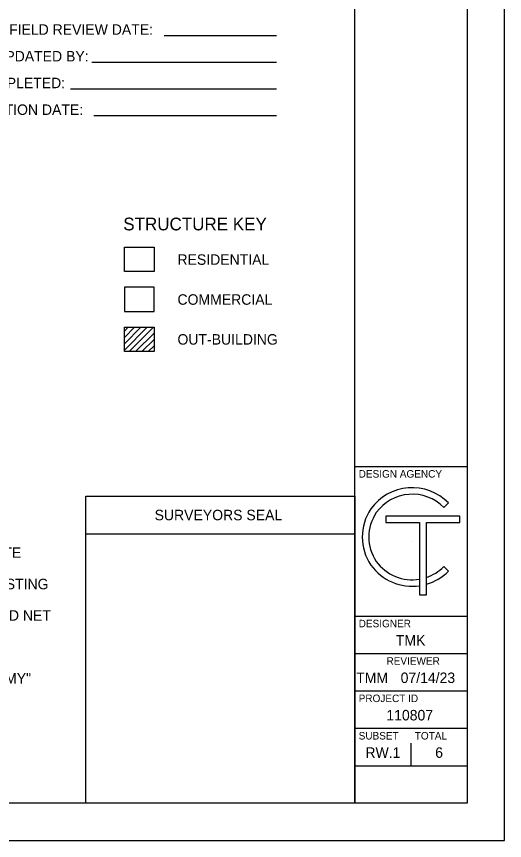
# Model space of a CAD drawing. Extents: x 0 to 34, y 0 to 22.
# Drawn here: x 27.47 to 34, y 0 to 11.01 of the extents above; entities that cross this region are included whole.
import ezdxf

# ---------------------------------------------------------------- set-up
doc = ezdxf.new("R2010")
doc.units = 0
for name, color, linetype in [('SC_Shading1', 7, 'Continuous'), ('SH_Border', 7, 'Continuous'), ('SH_Cut_Line', 7, 'Continuous'), ('SH_Data', 7, 'Continuous'), ('SH_Text', 7, 'Continuous')]:
    doc.layers.add(name, color=color, linetype=linetype)

msp = doc.modelspace()

# ---------------------------------------------------------------- linework, layer by layer
at = {"layer": 'SC_Shading1'}
msp.add_lwpolyline([(28.918, 7.069), (29.315, 7.069), (29.315, 7.395), (28.918, 7.395)], close=True, dxfattribs=at)
at = {"layer": 'SH_Border'}
for p, q in [((32, 0.5), (32, 21.5)), ((32, 5), (33.5, 5)), ((32, 3), (33.5, 3)), ((32, 2.5), (33.5, 2.5)), ((32, 2), (33.5, 2)), ((32, 1.5), (33.5, 1.5)), ((32, 1), (33.5, 1))]:
    msp.add_line(p, q, dxfattribs=at)
msp.add_lwpolyline([(1.5, 21.5), (33.5, 21.5), (33.5, 0.5), (1.5, 0.5)], close=True, dxfattribs=at)
at = {"layer": 'SH_Cut_Line'}
msp.add_lwpolyline([(0, 0), (34, 0), (34, 22), (0, 22)], close=True, dxfattribs=at)
at = {"layer": 'SH_Data'}
for p, q in [((28.4, 4.1), (32, 4.1)), ((32.75, 4), (32.75, 4)), ((32.75, 1), (32.75, 1.3))]:
    msp.add_line(p, q, dxfattribs=at)
msp.add_lwpolyline([(28.4, 4.6), (32, 4.6), (32, 0.5), (28.4, 0.5)], close=True, dxfattribs=at)
at = {"layer": 'SH_Text'}
for p, q in [((29.45, 10.758), (30.953, 10.758)), ((28.48, 10.401), (30.953, 10.401)), ((28.195, 10.044), (30.953, 10.044)), ((28.51, 9.687), (30.953, 9.687)), ((28.918, 6.858), (28.919, 6.86)), ((28.918, 6.808), (28.969, 6.86)), ((28.918, 6.724), (29.054, 6.86)), ((28.918, 6.639), (29.138, 6.86)), ((28.918, 6.554), (29.223, 6.86)), ((28.982, 6.534), (29.308, 6.86)), ((29.067, 6.534), (29.315, 6.782)), ((29.151, 6.534), (29.315, 6.697)), ((29.236, 6.534), (29.315, 6.612)), ((28.918, 6.538), (28.922, 6.534)), ((33.249, 4.513), (33.187, 4.452)), ((33.249, 4.513), (33.187, 4.452)), ((33.402, 4.333), (32.414, 4.333)), ((32.414, 4.333), (32.414, 4.251)), ((33.402, 4.251), (33.402, 4.333)), ((32.414, 4.251), (32.863, 4.251)), ((32.863, 4.251), (32.863, 3.285)), ((32.956, 3.285), (32.956, 4.251)), ((32.956, 4.251), (33.402, 4.251)), ((33.187, 3.66), (33.249, 3.599)), ((33.187, 3.66), (33.249, 3.599)), ((32.863, 3.493), (32.863, 3.405)), ((32.863, 3.493), (32.863, 3.405)), ((32.956, 3.425), (32.956, 3.516)), ((32.956, 3.425), (32.956, 3.516)), ((32.863, 3.285), (32.956, 3.285))]:
    msp.add_line(p, q, dxfattribs=at)
for points in [[(28.918, 7.93), (29.315, 7.93), (29.315, 7.605), (28.918, 7.605)], [(28.918, 6.86), (29.315, 6.86), (29.315, 6.534), (28.918, 6.534)], [(32.863, 4.251), (32.863, 3.285), (32.956, 3.285), (32.956, 4.251), (33.402, 4.251), (33.402, 4.333), (32.414, 4.333), (32.414, 4.251)]]:
    msp.add_lwpolyline(points, close=True, dxfattribs=at)
for centre, radius, start, end in [((32.766, 4.035), 0.68, 44.7027, 144.3276), ((32.766, 4.035), 0.68, 44.7027, 144.3276), ((32.766, 4.035), 0.593, 44.7362, 144.1102), ((32.766, 4.035), 0.593, 44.7362, 144.1102), ((32.764, 4.056), 0.666, 145.7329, 214.2671), ((32.764, 4.056), 0.666, 145.7329, 214.2671), ((32.764, 4.056), 0.579, 145.7266, 214.2734), ((32.764, 4.056), 0.579, 145.7266, 214.2734), ((32.766, 4.078), 0.68, 215.6724, 278.2613), ((32.766, 4.078), 0.68, 215.6724, 278.2613), ((32.766, 4.078), 0.593, 215.8898, 279.4882), ((32.766, 4.078), 0.593, 215.8898, 279.4882), ((32.766, 4.078), 0.593, 288.6992, 315.2638), ((32.766, 4.078), 0.593, 288.6992, 315.2638), ((32.766, 4.078), 0.68, 286.2291, 315.2973), ((32.766, 4.078), 0.68, 286.2291, 315.2973)]:
    msp.add_arc(centre, radius, start, end, dxfattribs=at)

# ---------------------------------------------------------------- texts
at = {"layer": 'SH_Data'}
for s, height, p in [('DESIGN AGENCY', 0.1, (32.05, 4.85)), ('SURVEYORS SEAL', 0.14, (29.321, 4.28)), ('BETWEEN MARCH, 2022 AND MAY, 2022. THE RESULTS OF THAT SURVEY ARE CONTAINED HEREIN. SEE THE SURVEY PARAMETERS NOTE', 0.14, (14.869, 3.778)), ('I HAVE REESTABLISHED THE LOCATIONS OF THE EXISTING PROPERTY LINES, THE EXISTING CENTERLINE RIGHT OF WAY, AND THE EXISTING', 0.14, (14.869, 3.358)), ('ESTABLISHED THE PROPOSED PROPERTY LINES, CALCULATED THE GROSS TAKE, PRESENT ROADWAY OCCUPIED (PRO), NET TAKE AND NET', 0.14, (14.869, 2.938)), ('DESIGNER', 0.1, (32.05, 2.85)), ('TMK', 0.14, (32.547, 2.605)), ('REVIEWER', 0.1, (32.422, 2.35)), ('THE OHIO ADMINISTRATIVE CODE CHAPTER 4733-37 STANDARDS FOR BOUNDARY SURVEYS, UNLESS SO NOTED. THE WORDS "I" AND "MY"', 0.14, (14.869, 2.098)), ('TMM', 0.14, (32.017, 2.105)), ('07/14/23', 0.14, (32.611, 2.105)), ('PROJECT ID', 0.1, (32.05, 1.85)), ('110807', 0.14, (32.42, 1.605)), ('SUBSET', 0.1, (32.05, 1.35)), ('TOTAL', 0.1, (32.8, 1.35)), ('RW.1', 0.14, (32.14, 1.105)), ('6', 0.14, (33.073, 1.105))]:
    msp.add_text(s, height=height, dxfattribs=at).set_placement(p)
at = {"layer": 'SH_Text'}
for s, height, p in [('TRACINGS FIELD REVIEW DATE:', 0.14, (26.356, 10.768)), ('OWNERSHIP UPDATED BY:', 0.14, (25.984, 10.411)), ('DATE COMPLETED:', 0.14, (26.356, 10.054)), ('PLAN COMPLETION DATE:', 0.14, (25.984, 9.697)), ('STRUCTURE KEY', 0.17, (28.902, 8.154)), ('RESIDENTIAL', 0.14, (29.627, 7.694)), ('COMMERCIAL', 0.14, (29.627, 7.16)), ('OUT-BUILDING', 0.14, (29.627, 6.627))]:
    msp.add_text(s, height=height, dxfattribs=at).set_placement(p)

doc.saveas('drawing.dxf')
